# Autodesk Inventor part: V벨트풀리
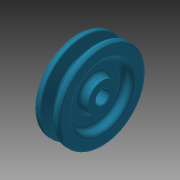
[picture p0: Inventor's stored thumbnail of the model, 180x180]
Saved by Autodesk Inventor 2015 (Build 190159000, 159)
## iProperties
Created: 2015-11
Part Number: V벨트풀리
Material: 강철, 탄소
Document SubType Name: Modeling
Designer: mduedu
Density: 7.87 g/cm^3
Mass: 380.065 g
Surface Area: 160.69 cm^2
Volume: 48.2929 cm^3
Appearance: 터키옥색
Author: mduedu
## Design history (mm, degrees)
sketch "스케치1"
  geometry: L1 (-9.5, 0)-(9.5, 0); L2 (0, 0)-(0, 35.7); L3 (-4.825, 35.7)-(-9.5, 35.7); L4 (-9.5, 35.7)-(-9.5, 0); L5 (0, 26.7)-(-2.074, 26.7); L6 (-2.074, 26.7)-(-4.825, 35.7); L7 (4.825, 35.7)-(9.5, 35.7); L8 (9.5, 35.7)-(9.5, 0); L9 (0, 26.7)-(2.074, 26.7); L10 (2.074, 26.7)-(4.825, 35.7); L11 (-9.5, 33)-(9.5, 33); 3 further points
  constraints: 22 end point, 7 point on line, 4 perpendicular, 3 symmetric about line, 1 coincident, 1 horizontal, 1 horizontal alignment, 1 midpoint, 1 vertical
  dimensions: "d0" = 19 distance of L1.start L1.end; "d2" = 71.4 diameter of L2.end L1 (derived); "d3" = 34 deg angle of L10 L6; "d4" = 6.3 distance between parallel lines of L11 L9; "d5" = 2.7 distance between parallel lines of L7 L11; "d6" = 8 distance of point (4, 33) point (-4, 33); "d7" = 66 diameter of L11 L1
revolve "회전1" sketch "스케치1" stored, may be unused: angle "d8" = 90 deg
sketch "스케치2"
  geometry: C1 r 22 at (0, 0); C2 r 11 at (0, 0); 1 further point
  constraints: 2 centre point, 2 coincident
  dimensions: "d9" = 44 diameter of C1; "d10" = 22 diameter of C2
extrude "돌출1" cut sketch "스케치2" distance "d11" = 6; taper "d12" = 0 deg
fillet "모깎기1" dims "d13" = 3
fillet "모깎기2" dims "d14" = 3
fillet "모깎기3" dims "d15" = 1, "d16" = 0.5, "d17" = 2
hole "구멍1" diameter "d20" = 10; stored, may be unused: countersink angle "d24" = 90 deg, drill point angle "d26" = 118 deg; dims "d18" = 10, "d19" = 10, "d21" = 6, "d22" = 4, "d23" = 2, "d25" = 8
sketch "스케치3"
  geometry: L1 (-1.5, 0)-(1.5, 0); L2 (1.5, 0)-(1.5, 6.4); L3 (1.5, 6.4)-(-1.5, 6.4); L4 (-1.5, 6.4)-(-1.5, 0); 2 further points
  constraints: 8 end point, 2 parallel, 1 coincident, 1 horizontal, 1 midpoint, 1 perpendicular
  dimensions: "d27" = 3 distance of L2.end L3.end; "d29" = 6.4 distance of L3.end L1.start
extrude "돌출2" cut sketch "스케치3" stored distance "d30" = 6; taper "d31" = 0 deg
chamfer "모따기1" distance "d32" = 0.5; stored, may be unused: second distance "d33" = 2, angle "d34" = 45 deg
node "솔리드1"
mirror "대칭1"
